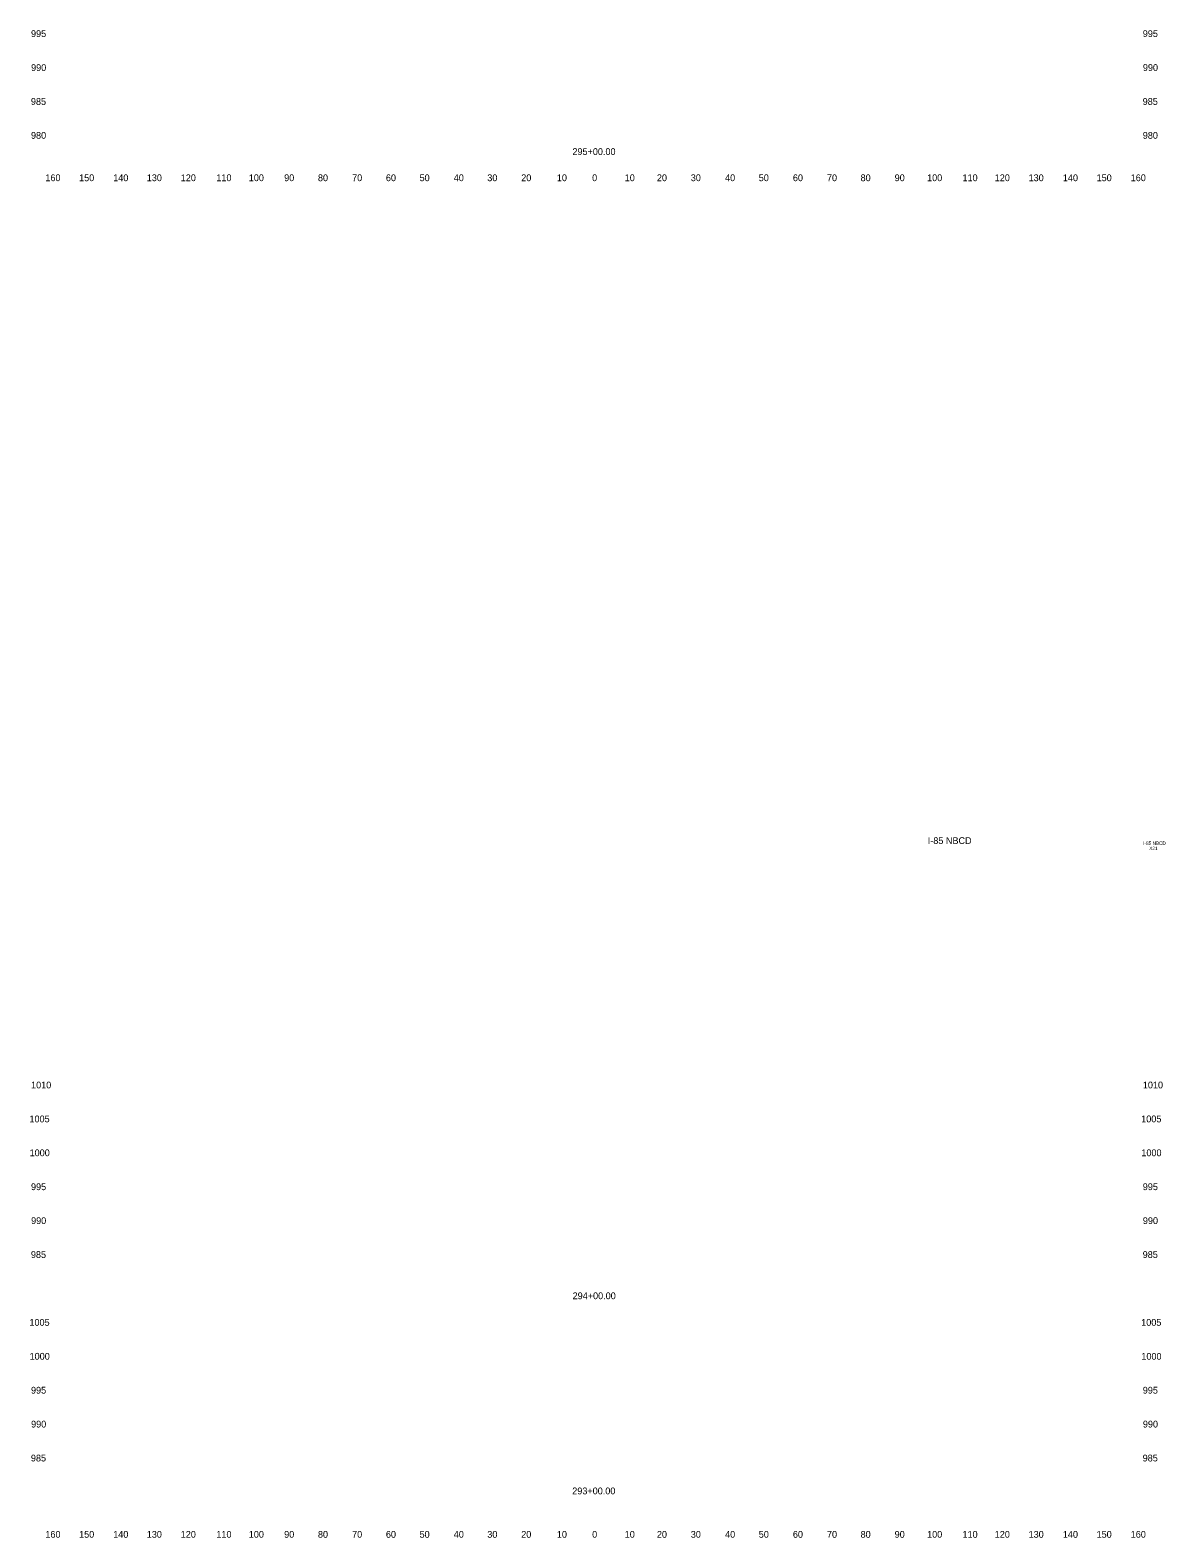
# Model space of a CAD drawing. Extents: x 4994 to 6358, y 4997 to 8804.
# Drawn here: x 6023.6 to 6358.2, y 4997.5 to 5442 of the extents above; entities that cross this region are included whole.
import ezdxf

# ---------------------------------------------------------------- set-up
doc = ezdxf.new("R2010")
doc.units = 0
for name, color, linetype in [('RD_SHT_ID', 7, 'Continuous'), ('RD_XS_TX_Offset', 7, 'Continuous'), ('RD_XS_TX_Station', 7, 'Continuous')]:
    doc.layers.add(name, color=color, linetype=linetype)

msp = doc.modelspace()

# ---------------------------------------------------------------- texts
at = {"layer": 'RD_SHT_ID'}
for s, height, p in [('I-85 NBCD', 2, (6288.26, 5202.06)), ('I-85 NBCD', 1, (6351.77, 5201.8)), ('X21', 1, (6353.57, 5200.3))]:
    msp.add_text(s, height=height, dxfattribs=at).set_placement(p)
at = {"layer": 'RD_XS_TX_Offset'}
for s, p in [('995', (6023.86, 5440)), ('995', (6351.66, 5440)), ('990', (6023.89, 5430)), ('990', (6351.69, 5430)), ('985', (6023.83, 5420)), ('985', (6351.63, 5420)), ('980', (6023.86, 5410)), ('980', (6351.66, 5410)), ('160', (6028.1, 5397.5)), ('150', (6038.04, 5397.5)), ('140', (6048.1, 5397.5)), ('130', (6057.99, 5397.5)), ('120', (6068.01, 5397.5)), ('110', (6078.51, 5397.5)), ('100', (6088.07, 5397.5)), ('90', (6098.5, 5397.5)), ('80', (6108.46, 5397.5)), ('70', (6118.54, 5397.5)), ('60', (6128.5, 5397.5)), ('50', (6138.43, 5397.5)), ('40', (6148.5, 5397.5)), ('30', (6158.39, 5397.5)), ('20', (6168.4, 5397.5)), ('10', (6178.91, 5397.5)), ('0', (6189.3, 5397.5)), ('0', (6189.3, 5397.5)), ('10', (6198.91, 5397.5)), ('20', (6208.4, 5397.5)), ('30', (6218.39, 5397.5)), ('40', (6228.5, 5397.5)), ('50', (6238.43, 5397.5)), ('60', (6248.5, 5397.5)), ('70', (6258.54, 5397.5)), ('80', (6268.46, 5397.5)), ('90', (6278.5, 5397.5)), ('100', (6288.07, 5397.5)), ('110', (6298.51, 5397.5)), ('120', (6308.01, 5397.5)), ('130', (6317.99, 5397.5)), ('140', (6328.1, 5397.5)), ('150', (6338.04, 5397.5)), ('160', (6348.1, 5397.5)), ('1010', (6023.88, 5130)), ('1010', (6351.68, 5130)), ('1005', (6023.4, 5120)), ('1005', (6351.2, 5120)), ('1000', (6023.44, 5110)), ('1000', (6351.24, 5110)), ('995', (6023.86, 5100)), ('995', (6351.66, 5100)), ('990', (6023.89, 5090)), ('990', (6351.69, 5090)), ('985', (6023.83, 5080)), ('985', (6351.63, 5080)), ('1005', (6023.4, 5060)), ('1005', (6351.2, 5060)), ('1000', (6023.44, 5050)), ('1000', (6351.24, 5050)), ('995', (6023.86, 5040)), ('995', (6351.66, 5040)), ('990', (6023.89, 5030)), ('990', (6351.69, 5030)), ('985', (6023.83, 5020)), ('985', (6351.63, 5020)), ('160', (6028.1, 4997.5)), ('150', (6038.04, 4997.5)), ('140', (6048.1, 4997.5)), ('130', (6057.99, 4997.5)), ('120', (6068.01, 4997.5)), ('110', (6078.51, 4997.5)), ('100', (6088.07, 4997.5)), ('90', (6098.5, 4997.5)), ('80', (6108.46, 4997.5)), ('70', (6118.54, 4997.5)), ('60', (6128.5, 4997.5)), ('50', (6138.43, 4997.5)), ('40', (6148.5, 4997.5)), ('30', (6158.39, 4997.5)), ('20', (6168.4, 4997.5)), ('10', (6178.91, 4997.5)), ('0', (6189.3, 4997.5)), ('0', (6189.3, 4997.5)), ('10', (6198.91, 4997.5)), ('20', (6208.4, 4997.5)), ('30', (6218.39, 4997.5)), ('40', (6228.5, 4997.5)), ('50', (6238.43, 4997.5)), ('60', (6248.5, 4997.5)), ('70', (6258.54, 4997.5)), ('80', (6268.46, 4997.5)), ('90', (6278.5, 4997.5)), ('100', (6288.07, 4997.5)), ('110', (6298.51, 4997.5)), ('120', (6308.01, 4997.5)), ('130', (6317.99, 4997.5)), ('140', (6328.1, 4997.5)), ('150', (6338.04, 4997.5)), ('160', (6348.1, 4997.5))]:
    msp.add_text(s, height=2, dxfattribs=at).set_placement(p)
at = {"layer": 'RD_XS_TX_Station'}
for s, p in [('295+00.00', (6183.49, 5405.22)), ('294+00.00', (6183.55, 5067.84)), ('293+00.00', (6183.44, 5010.31))]:
    msp.add_text(s, height=2, dxfattribs=at).set_placement(p)

doc.saveas('drawing.dxf')
